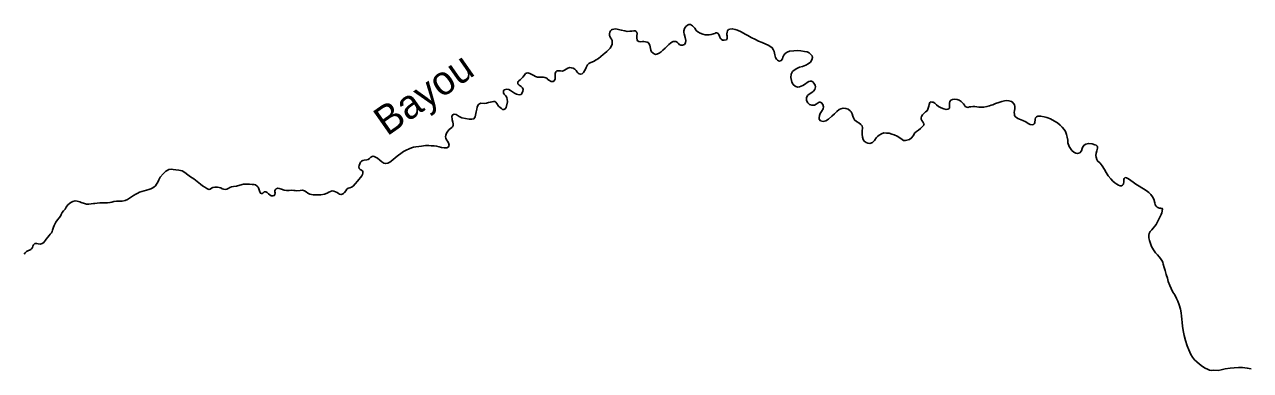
# Model space of a CAD drawing. Extents: x -939622 to -934222, y 1383701 to 1385301.
# Drawn here: x -936352.7 to -936285.2, y 1384424.2 to 1384443.3 of the extents above; entities that cross this region are included whole.
import ezdxf

# ---------------------------------------------------------------- set-up
doc = ezdxf.new("R2010")
doc.units = 0
doc.layers.add('2', color=7, linetype='Continuous')
doc.layers.add('9', color=7, linetype='Continuous')

msp = doc.modelspace()

# ---------------------------------------------------------------- linework, layer by layer
at = {"layer": '2'}
for points in [[(-936316.595, 1384442.127), (-936316.493, 1384442.124), (-936316.389, 1384442.173), (-936316.329, 1384442.265), (-936316.315, 1384442.395), (-936316.348, 1384442.56), (-936316.411, 1384442.75), (-936316.423, 1384442.822), (-936316.417, 1384442.915), (-936316.385, 1384443.046), (-936316.316, 1384443.156), (-936316.229, 1384443.238), (-936316.158, 1384443.264), (-936316.062, 1384443.27), (-936315.943, 1384443.202), (-936315.827, 1384443.074), (-936315.745, 1384442.941), (-936315.655, 1384442.863), (-936315.527, 1384442.798), (-936315.384, 1384442.746), (-936315.245, 1384442.708), (-936315.137, 1384442.703), (-936315.023, 1384442.701), (-936314.924, 1384442.713), (-936314.793, 1384442.757), (-936314.722, 1384442.783), (-936314.669, 1384442.803), (-936314.63, 1384442.81), (-936314.575, 1384442.8), (-936314.538, 1384442.771), (-936314.513, 1384442.736), (-936314.487, 1384442.677), (-936314.448, 1384442.579), (-936314.413, 1384442.505), (-936314.372, 1384442.461), (-936314.292, 1384442.403), (-936314.199, 1384442.404), (-936314.08, 1384442.423), (-936314.04, 1384442.502), (-936314.042, 1384442.65), (-936314.056, 1384442.7), (-936314.061, 1384442.754), (-936314.045, 1384442.839), (-936314.015, 1384442.924), (-936313.963, 1384442.989), (-936313.886, 1384443.019), (-936313.76, 1384443.032), (-936313.606, 1384443.001), (-936313.47, 1384442.964), (-936313.272, 1384442.874), (-936313.054, 1384442.743), (-936312.896, 1384442.658), (-936312.709, 1384442.55), (-936312.486, 1384442.435), (-936312.318, 1384442.356), (-936312.105, 1384442.276), (-936311.908, 1384442.195), (-936311.785, 1384442.13), (-936311.638, 1384442.045), (-936311.558, 1384441.985), (-936311.501, 1384441.899), (-936311.459, 1384441.78), (-936311.419, 1384441.595), (-936311.379, 1384441.452), (-936311.331, 1384441.366), (-936311.275, 1384441.299), (-936311.219, 1384441.265), (-936311.153, 1384441.246), (-936311.058, 1384441.279), (-936311.001, 1384441.372), (-936310.971, 1384441.472), (-936310.917, 1384441.576), (-936310.839, 1384441.663), (-936310.737, 1384441.745), (-936310.606, 1384441.794), (-936310.376, 1384441.811), (-936310.151, 1384441.831), (-936309.979, 1384441.812), (-936309.777, 1384441.78), (-936309.639, 1384441.764), (-936309.526, 1384441.707), (-936309.442, 1384441.635), (-936309.364, 1384441.547), (-936309.337, 1384441.455), (-936309.378, 1384441.327), (-936309.455, 1384441.195), (-936309.572, 1384441.098), (-936309.713, 1384441.021), (-936309.9, 1384440.964), (-936310.055, 1384440.919), (-936310.212, 1384440.842), (-936310.344, 1384440.756), (-936310.437, 1384440.675), (-936310.508, 1384440.531), (-936310.538, 1384440.352), (-936310.505, 1384440.188), (-936310.472, 1384440.084), (-936310.408, 1384439.966), (-936310.3, 1384439.87), (-936310.172, 1384439.817), (-936310.049, 1384439.833)], [(-936323.516, 1384440.418), (-936323.515, 1384440.49), (-936323.509, 1384440.566), (-936323.479, 1384440.654), (-936323.417, 1384440.713), (-936323.331, 1384440.722), (-936323.21, 1384440.708), (-936323.099, 1384440.703), (-936322.992, 1384440.746), (-936322.913, 1384440.815), (-936322.816, 1384440.866), (-936322.697, 1384440.894), (-936322.622, 1384440.888), (-936322.513, 1384440.861), (-936322.43, 1384440.813), (-936322.362, 1384440.74), (-936322.293, 1384440.652), (-936322.24, 1384440.597), (-936322.184, 1384440.551), (-936322.114, 1384440.532), (-936322.028, 1384440.556), (-936321.946, 1384440.616), (-936321.839, 1384440.815), (-936321.803, 1384440.909), (-936321.766, 1384440.977), (-936321.729, 1384441.047), (-936321.663, 1384441.122), (-936321.547, 1384441.183), (-936321.402, 1384441.227), (-936321.249, 1384441.319), (-936321.122, 1384441.402), (-936320.994, 1384441.503), (-936320.868, 1384441.615), (-936320.772, 1384441.694), (-936320.658, 1384441.791), (-936320.568, 1384441.878), (-936320.481, 1384441.971), (-936320.44, 1384442.027), (-936320.407, 1384442.109), (-936320.376, 1384442.167), (-936320.363, 1384442.225), (-936320.365, 1384442.3), (-936320.377, 1384442.387), (-936320.413, 1384442.461), (-936320.463, 1384442.541), (-936320.508, 1384442.62), (-936320.522, 1384442.668), (-936320.513, 1384442.758), (-936320.497, 1384442.846), (-936320.47, 1384442.913), (-936320.417, 1384442.969), (-936320.364, 1384442.998), (-936320.278, 1384443.019), (-936320.167, 1384443.023), (-936319.871, 1384442.967), (-936319.683, 1384442.922), (-936319.55, 1384442.893), (-936319.391, 1384442.899), (-936319.287, 1384442.911), (-936319.179, 1384442.924), (-936319.113, 1384442.923), (-936319.052, 1384442.892), (-936319.011, 1384442.839), (-936318.996, 1384442.756), (-936319.006, 1384442.671), (-936319.011, 1384442.572), (-936319.018, 1384442.508), (-936319.003, 1384442.424), (-936318.969, 1384442.371), (-936318.91, 1384442.337), (-936318.817, 1384442.319), (-936318.709, 1384442.335), (-936318.619, 1384442.332), (-936318.541, 1384442.323), (-936318.453, 1384442.302), (-936318.398, 1384442.27), (-936318.345, 1384442.215), (-936318.303, 1384442.123), (-936318.285, 1384442.037), (-936318.234, 1384441.852), (-936318.201, 1384441.772), (-936318.123, 1384441.684), (-936318.062, 1384441.647), (-936317.98, 1384441.623), (-936317.903, 1384441.637), (-936317.784, 1384441.686), (-936317.673, 1384441.759), (-936317.577, 1384441.853), (-936317.46, 1384441.971), (-936317.333, 1384442.102), (-936317.251, 1384442.177), (-936317.163, 1384442.243), (-936317.081, 1384442.3), (-936317.016, 1384442.329), (-936316.95, 1384442.338), (-936316.872, 1384442.331), (-936316.823, 1384442.312), (-936316.78, 1384442.283), (-936316.724, 1384442.216), (-936316.677, 1384442.163), (-936316.595, 1384442.127)], [(-936329.122, 1384437.713), (-936329.118, 1384437.788), (-936329.14, 1384437.896), (-936329.174, 1384438.009), (-936329.188, 1384438.075), (-936329.189, 1384438.096), (-936329.191, 1384438.159), (-936329.193, 1384438.216), (-936329.153, 1384438.299), (-936329.079, 1384438.334), (-936328.961, 1384438.308), (-936328.799, 1384438.193), (-936328.652, 1384438.12), (-936328.444, 1384438.082), (-936328.242, 1384438.062), (-936328.1, 1384438.045), (-936327.984, 1384438.079), (-936327.91, 1384438.19), (-936327.868, 1384438.463), (-936327.821, 1384438.605), (-936327.801, 1384438.708), (-936327.771, 1384438.8), (-936327.731, 1384438.864), (-936327.675, 1384438.899), (-936327.595, 1384438.935), (-936327.394, 1384438.924), (-936327.298, 1384438.936), (-936327.182, 1384438.964), (-936327.078, 1384438.992), (-936326.985, 1384439.013), (-936326.913, 1384439.024), (-936326.838, 1384439.018), (-936326.78, 1384438.984), (-936326.721, 1384438.914), (-936326.626, 1384438.778), (-936326.536, 1384438.697), (-936326.471, 1384438.633), (-936326.401, 1384438.593), (-936326.329, 1384438.593), (-936326.258, 1384438.619), (-936326.2, 1384438.697), (-936326.144, 1384439.008), (-936326.152, 1384439.149), (-936326.17, 1384439.227), (-936326.186, 1384439.278), (-936326.243, 1384439.357), (-936326.312, 1384439.436), (-936326.346, 1384439.489), (-936326.361, 1384439.561), (-936326.356, 1384439.615), (-936326.31, 1384439.668), (-936326.239, 1384439.697), (-936326.164, 1384439.706), (-936326.062, 1384439.688), (-936325.964, 1384439.634), (-936325.752, 1384439.479), (-936325.645, 1384439.431), (-936325.563, 1384439.41), (-936325.452, 1384439.396), (-936325.383, 1384439.416), (-936325.326, 1384439.508), (-936325.287, 1384439.603), (-936325.281, 1384439.687), (-936325.308, 1384439.774), (-936325.379, 1384439.847), (-936325.441, 1384439.893), (-936325.493, 1384439.924), (-936325.53, 1384439.959), (-936325.562, 1384440.009), (-936325.569, 1384440.051), (-936325.567, 1384440.087), (-936325.551, 1384440.13), (-936325.507, 1384440.161), (-936325.434, 1384440.215), (-936325.361, 1384440.29), (-936325.289, 1384440.37), (-936325.22, 1384440.466), (-936325.183, 1384440.524), (-936325.136, 1384440.568), (-936325.089, 1384440.594), (-936325.014, 1384440.602), (-936324.911, 1384440.579), (-936324.792, 1384440.516), (-936324.682, 1384440.457), (-936324.587, 1384440.406), (-936324.475, 1384440.374), (-936324.373, 1384440.365), (-936324.283, 1384440.371), (-936324.169, 1384440.375), (-936324.078, 1384440.354), (-936323.977, 1384440.306), (-936323.909, 1384440.248), (-936323.829, 1384440.185), (-936323.771, 1384440.145), (-936323.722, 1384440.128), (-936323.677, 1384440.124), (-936323.626, 1384440.126), (-936323.582, 1384440.151), (-936323.542, 1384440.201), (-936323.519, 1384440.25), (-936323.516, 1384440.418)], [(-936310.049, 1384439.833), (-936309.866, 1384439.915), (-936309.73, 1384439.997), (-936309.634, 1384440.067), (-936309.537, 1384440.13), (-936309.459, 1384440.154), (-936309.393, 1384440.15), (-936309.317, 1384440.105), (-936309.258, 1384440.041), (-936309.191, 1384439.932), (-936309.179, 1384439.83), (-936309.219, 1384439.687), (-936309.288, 1384439.597), (-936309.379, 1384439.528), (-936309.519, 1384439.424), (-936309.607, 1384439.355), (-936309.675, 1384439.22), (-936309.679, 1384439.076), (-936309.606, 1384438.949), (-936309.501, 1384438.865), (-936309.371, 1384438.824), (-936309.239, 1384438.832), (-936309.132, 1384438.886), (-936309.035, 1384438.95), (-936308.967, 1384438.982), (-936308.914, 1384438.993), (-936308.841, 1384438.959), (-936308.774, 1384438.853), (-936308.734, 1384438.734), (-936308.76, 1384438.622), (-936308.843, 1384438.472), (-936308.911, 1384438.364), (-936308.959, 1384438.26), (-936308.979, 1384438.133), (-936308.976, 1384438.061), (-936308.892, 1384437.962), (-936308.759, 1384437.93), (-936308.607, 1384437.959), (-936308.454, 1384438.058), (-936308.27, 1384438.218), (-936308.136, 1384438.348), (-936308.005, 1384438.473), (-936307.88, 1384438.583), (-936307.782, 1384438.631), (-936307.645, 1384438.654), (-936307.503, 1384438.65), (-936307.376, 1384438.603), (-936307.274, 1384438.519), (-936307.209, 1384438.452), (-936307.157, 1384438.355), (-936307.12, 1384438.226), (-936307.09, 1384438.131), (-936307.026, 1384438.01), (-936306.912, 1384437.924), (-936306.796, 1384437.849), (-936306.676, 1384437.76), (-936306.613, 1384437.678), (-936306.585, 1384437.577), (-936306.597, 1384437.39), (-936306.598, 1384437.218), (-936306.587, 1384437.068), (-936306.555, 1384436.94), (-936306.498, 1384436.845), (-936306.385, 1384436.765), (-936306.287, 1384436.726), (-936306.182, 1384436.718), (-936306.042, 1384436.768), (-936305.935, 1384436.873), (-936305.826, 1384437.022), (-936305.759, 1384437.105), (-936305.675, 1384437.18), (-936305.533, 1384437.248), (-936305.405, 1384437.292), (-936305.264, 1384437.29), (-936305.119, 1384437.274), (-936304.98, 1384437.231), (-936304.846, 1384437.184), (-936304.685, 1384437.123), (-936304.529, 1384437.032), (-936304.403, 1384436.937), (-936304.323, 1384436.886), (-936304.226, 1384436.871), (-936303.994, 1384436.927), (-936303.883, 1384437.021), (-936303.797, 1384437.132), (-936303.697, 1384437.292), (-936303.621, 1384437.37), (-936303.51, 1384437.449), (-936303.399, 1384437.531), (-936303.317, 1384437.612), (-936303.247, 1384437.678), (-936303.216, 1384437.73), (-936303.202, 1384437.76), (-936303.2, 1384437.788), (-936303.223, 1384437.841), (-936303.261, 1384437.906), (-936303.326, 1384437.985), (-936303.362, 1384438.059), (-936303.361, 1384438.128), (-936303.336, 1384438.195), (-936303.285, 1384438.287)], [(-936303.285, 1384438.287), (-936303.21, 1384438.365), (-936303.111, 1384438.449), (-936303.035, 1384438.518), (-936302.993, 1384438.607), (-936302.929, 1384438.763), (-936302.911, 1384438.862), (-936302.906, 1384438.908), (-936302.887, 1384438.963), (-936302.838, 1384439.003), (-936302.774, 1384438.999), (-936302.693, 1384438.987), (-936302.61, 1384438.933), (-936302.511, 1384438.849), (-936302.403, 1384438.756), (-936302.25, 1384438.674), (-936302.101, 1384438.622), (-936301.989, 1384438.59), (-936301.897, 1384438.599), (-936301.828, 1384438.619), (-936301.8, 1384438.662), (-936301.79, 1384438.744), (-936301.802, 1384438.837), (-936301.802, 1384438.933), (-936301.781, 1384439.024), (-936301.718, 1384439.095), (-936301.623, 1384439.144), (-936301.537, 1384439.162), (-936301.377, 1384439.143), (-936301.267, 1384439.096), (-936301.163, 1384439.03), (-936301.074, 1384438.961), (-936301.024, 1384438.893), (-936300.976, 1384438.82), (-936300.929, 1384438.758), (-936300.846, 1384438.71), (-936300.789, 1384438.703), (-936300.688, 1384438.724), (-936300.613, 1384438.742), (-936300.518, 1384438.757), (-936300.406, 1384438.749), (-936300.183, 1384438.72), (-936300.045, 1384438.713), (-936299.907, 1384438.72), (-936299.74, 1384438.747), (-936299.597, 1384438.794), (-936299.505, 1384438.818), (-936299.416, 1384438.848), (-936299.262, 1384438.914), (-936299.087, 1384438.974), (-936298.923, 1384439.031), (-936298.774, 1384439.063), (-936298.64, 1384439.073), (-936298.525, 1384439.065), (-936298.392, 1384439.031), (-936298.309, 1384438.964), (-936298.218, 1384438.835), (-936298.203, 1384438.751), (-936298.195, 1384438.622), (-936298.214, 1384438.534), (-936298.228, 1384438.428), (-936298.225, 1384438.338), (-936298.211, 1384438.26), (-936298.16, 1384438.184), (-936298.025, 1384438.098), (-936297.766, 1384437.978), (-936297.598, 1384437.899), (-936297.473, 1384437.819), (-936297.356, 1384437.757), (-936297.239, 1384437.746), (-936297.179, 1384437.76), (-936297.129, 1384437.795), (-936297.098, 1384437.853), (-936297.078, 1384438.055), (-936297.053, 1384438.125), (-936297.01, 1384438.187), (-936296.933, 1384438.219), (-936296.777, 1384438.219), (-936296.581, 1384438.174), (-936296.436, 1384438.149), (-936296.241, 1384438.068), (-936296.008, 1384437.938), (-936295.855, 1384437.85), (-936295.701, 1384437.717), (-936295.586, 1384437.615), (-936295.477, 1384437.492), (-936295.413, 1384437.371), (-936295.36, 1384437.217), (-936295.31, 1384437.059), (-936295.287, 1384436.903), (-936295.273, 1384436.75), (-936295.215, 1384436.554), (-936295.13, 1384436.43), (-936295.058, 1384436.336), (-936294.953, 1384436.243), (-936294.842, 1384436.178), (-936294.755, 1384436.163), (-936294.624, 1384436.197), (-936294.534, 1384436.3), (-936294.491, 1384436.434), (-936294.458, 1384436.537)], [(-936337.727, 1384434.112), (-936337.557, 1384434.124), (-936337.431, 1384434.137), (-936337.317, 1384434.111), (-936337.222, 1384434.054), (-936337.129, 1384433.979), (-936337.01, 1384433.919), (-936336.838, 1384433.886), (-936336.648, 1384433.878), (-936336.415, 1384433.891), (-936336.209, 1384433.926), (-936336.063, 1384433.979), (-936335.978, 1384434.024), (-936335.88, 1384434.069), (-936335.791, 1384434.096), (-936335.703, 1384434.084), (-936335.612, 1384434.057), (-936335.521, 1384434.006), (-936335.447, 1384433.957), (-936335.377, 1384433.918), (-936335.298, 1384433.902), (-936335.23, 1384433.926), (-936335.171, 1384433.961), (-936335.113, 1384434.02), (-936335.044, 1384434.109), (-936334.984, 1384434.196), (-936334.907, 1384434.243), (-936334.824, 1384434.273), (-936334.732, 1384434.31), (-936334.641, 1384434.37), (-936334.522, 1384434.482), (-936334.397, 1384434.631), (-936334.317, 1384434.733), (-936334.233, 1384434.838), (-936334.161, 1384434.934), (-936334.124, 1384435.001), (-936334.094, 1384435.071), (-936334.093, 1384435.15), (-936334.122, 1384435.206), (-936334.18, 1384435.24), (-936334.247, 1384435.271), (-936334.304, 1384435.335), (-936334.325, 1384435.428), (-936334.309, 1384435.509), (-936334.273, 1384435.601), (-936334.234, 1384435.677), (-936334.179, 1384435.733), (-936334.108, 1384435.769), (-936334.025, 1384435.796), (-936333.884, 1384435.813), (-936333.813, 1384435.83), (-936333.739, 1384435.881), (-936333.655, 1384435.959), (-936333.593, 1384436), (-936333.536, 1384436.011), (-936333.485, 1384435.998), (-936333.286, 1384435.902), (-936333.166, 1384435.798), (-936333.055, 1384435.696), (-936332.947, 1384435.631), (-936332.845, 1384435.61), (-936332.728, 1384435.635), (-936332.613, 1384435.684), (-936332.449, 1384435.804), (-936332.303, 1384435.938), (-936332.142, 1384436.061), (-936332.004, 1384436.162), (-936331.857, 1384436.263), (-936331.707, 1384436.35), (-936331.556, 1384436.418), (-936331.423, 1384436.477), (-936331.304, 1384436.514), (-936331.176, 1384436.536), (-936331.02, 1384436.553), (-936330.877, 1384436.567), (-936330.646, 1384436.596), (-936330.475, 1384436.602), (-936330.337, 1384436.592), (-936330.171, 1384436.576), (-936330.039, 1384436.566), (-936329.897, 1384436.537), (-936329.76, 1384436.5), (-936329.612, 1384436.472), (-936329.537, 1384436.468), (-936329.471, 1384436.474), (-936329.409, 1384436.503), (-936329.366, 1384436.558), (-936329.35, 1384436.616), (-936329.384, 1384436.741), (-936329.441, 1384436.833), (-936329.495, 1384436.918), (-936329.537, 1384436.998), (-936329.554, 1384437.078), (-936329.531, 1384437.179), (-936329.489, 1384437.282), (-936329.421, 1384437.399), (-936329.343, 1384437.486), (-936329.272, 1384437.542), (-936329.208, 1384437.59), (-936329.156, 1384437.64), (-936329.122, 1384437.713)], [(-936294.458, 1384436.537), (-936294.383, 1384436.627), (-936294.285, 1384436.675), (-936294.146, 1384436.713), (-936293.941, 1384436.687), (-936293.792, 1384436.644), (-936293.722, 1384436.613), (-936293.672, 1384436.57), (-936293.656, 1384436.534), (-936293.651, 1384436.456), (-936293.679, 1384436.311), (-936293.714, 1384436.183), (-936293.731, 1384436.056), (-936293.728, 1384435.966), (-936293.693, 1384435.832), (-936293.652, 1384435.755), (-936293.503, 1384435.622), (-936293.39, 1384435.475), (-936293.255, 1384435.281), (-936293.174, 1384435.106), (-936293.066, 1384434.935), (-936292.92, 1384434.769), (-936292.801, 1384434.64), (-936292.687, 1384434.536), (-936292.588, 1384434.464), (-936292.5, 1384434.419), (-936292.4, 1384434.386), (-936292.324, 1384434.383), (-936292.268, 1384434.412), (-936292.222, 1384434.477), (-936292.197, 1384434.61), (-936292.192, 1384434.727), (-936292.179, 1384434.785), (-936292.132, 1384434.832), (-936292.051, 1384434.828), (-936291.932, 1384434.769), (-936291.688, 1384434.579), (-936291.532, 1384434.473), (-936291.354, 1384434.358), (-936290.974, 1384434.131), (-936290.817, 1384434.019), (-936290.706, 1384433.911), (-936290.623, 1384433.781), (-936290.547, 1384433.637), (-936290.492, 1384433.437), (-936290.465, 1384433.336), (-936290.408, 1384433.259), (-936290.358, 1384433.21), (-936290.288, 1384433.173), (-936290.228, 1384433.157), (-936290.173, 1384433.147), (-936290.137, 1384433.139), (-936290.083, 1384433.135), (-936290.067, 1384433.102), (-936290.108, 1384432.899), (-936290.15, 1384432.796), (-936290.208, 1384432.655), (-936290.281, 1384432.511), (-936290.349, 1384432.389), (-936290.426, 1384432.248), (-936290.495, 1384432.164), (-936290.584, 1384432.044), (-936290.653, 1384431.96), (-936290.74, 1384431.858), (-936290.8, 1384431.754), (-936290.818, 1384431.66), (-936290.819, 1384431.515), (-936290.79, 1384431.375), (-936290.734, 1384431.205), (-936290.668, 1384431.039), (-936290.566, 1384430.844), (-936290.452, 1384430.688), (-936290.347, 1384430.577), (-936290.244, 1384430.461), (-936290.172, 1384430.373), (-936290.096, 1384430.261), (-936290.051, 1384430.166), (-936290.029, 1384430.062), (-936289.97, 1384429.886), (-936289.913, 1384429.723), (-936289.858, 1384429.493), (-936289.8, 1384429.287), (-936289.752, 1384429.114), (-936289.67, 1384428.894), (-936289.595, 1384428.716), (-936289.495, 1384428.524), (-936289.394, 1384428.365), (-936289.289, 1384428.176), (-936289.233, 1384428.031), (-936289.157, 1384427.826), (-936289.071, 1384427.588), (-936289.047, 1384427.384), (-936289.016, 1384427.198), (-936289.008, 1384427.036), (-936288.993, 1384426.841), (-936288.962, 1384426.638), (-936288.924, 1384426.41), (-936288.867, 1384426.126), (-936288.798, 1384425.861), (-936288.704, 1384425.566), (-936288.619, 1384425.334)], [(-936346.148, 1384434.111), (-936346.014, 1384434.145), (-936345.886, 1384434.179), (-936345.778, 1384434.21), (-936345.695, 1384434.245), (-936345.613, 1384434.299), (-936345.519, 1384434.38), (-936345.453, 1384434.472), (-936345.393, 1384434.588), (-936345.34, 1384434.707), (-936345.254, 1384434.854), (-936345.098, 1384435.039), (-936345.028, 1384435.107), (-936344.949, 1384435.179), (-936344.869, 1384435.232), (-936344.783, 1384435.271), (-936344.658, 1384435.29), (-936344.537, 1384435.275), (-936344.405, 1384435.261), (-936344.237, 1384435.245), (-936344.055, 1384435.208), (-936343.897, 1384435.12), (-936343.74, 1384434.995), (-936343.584, 1384434.879), (-936343.412, 1384434.767), (-936343.228, 1384434.619), (-936343.044, 1384434.477), (-936342.924, 1384434.388), (-936342.804, 1384434.301), (-936342.697, 1384434.229), (-936342.618, 1384434.189), (-936342.57, 1384434.182), (-936342.51, 1384434.205), (-936342.434, 1384434.249), (-936342.354, 1384434.29), (-936342.232, 1384434.315), (-936342.111, 1384434.301), (-936342.006, 1384434.286), (-936341.921, 1384434.261), (-936341.842, 1384434.218), (-936341.76, 1384434.188), (-936341.666, 1384434.173), (-936341.595, 1384434.187), (-936341.482, 1384434.253), (-936341.427, 1384434.291), (-936341.341, 1384434.333), (-936341.215, 1384434.348), (-936341.051, 1384434.368), (-936340.872, 1384434.422), (-936340.673, 1384434.467), (-936340.523, 1384434.471), (-936340.336, 1384434.465), (-936340.201, 1384434.46), (-936340.087, 1384434.445), (-936340.014, 1384434.426), (-936339.928, 1384434.366), (-936339.866, 1384434.298), (-936339.834, 1384434.212), (-936339.778, 1384434.051), (-936339.743, 1384433.977), (-936339.682, 1384433.955), (-936339.637, 1384433.962), (-936339.602, 1384433.984), (-936339.576, 1384434.015), (-936339.529, 1384434.041), (-936339.448, 1384434.046), (-936339.366, 1384434.018), (-936339.295, 1384433.948), (-936339.224, 1384433.887), (-936339.144, 1384433.836), (-936339.051, 1384433.82), (-936338.977, 1384433.841), (-936338.943, 1384433.908), (-936338.933, 1384433.992), (-936338.941, 1384434.049), (-936338.943, 1384434.112), (-936338.929, 1384434.167), (-936338.877, 1384434.223), (-936338.784, 1384434.246), (-936338.703, 1384434.237), (-936338.582, 1384434.195), (-936338.43, 1384434.134), (-936338.312, 1384434.116), (-936338.162, 1384434.117), (-936338.049, 1384434.136), (-936337.908, 1384434.128), (-936337.832, 1384434.121), (-936337.727, 1384434.112)], [(-936352.758, 1384430.615), (-936352.688, 1384430.695), (-936352.612, 1384430.755), (-936352.511, 1384430.812), (-936352.446, 1384430.838), (-936352.39, 1384430.867), (-936352.34, 1384430.91), (-936352.297, 1384430.981), (-936352.263, 1384431.051), (-936352.23, 1384431.136), (-936352.163, 1384431.195), (-936352.115, 1384431.209), (-936352.055, 1384431.208), (-936351.97, 1384431.186), (-936351.868, 1384431.174), (-936351.754, 1384431.195), (-936351.675, 1384431.261), (-936351.539, 1384431.433), (-936351.447, 1384431.553), (-936351.374, 1384431.637), (-936351.31, 1384431.708), (-936351.25, 1384431.791), (-936351.21, 1384431.861), (-936351.191, 1384431.931), (-936351.136, 1384432.095), (-936351.1, 1384432.195), (-936351, 1384432.382), (-936350.914, 1384432.505), (-936350.818, 1384432.61), (-936350.755, 1384432.708), (-936350.709, 1384432.803), (-936350.658, 1384432.903), (-936350.574, 1384432.993), (-936350.499, 1384433.101), (-936350.433, 1384433.211), (-936350.344, 1384433.325), (-936350.256, 1384433.406), (-936350.171, 1384433.468), (-936350.07, 1384433.519), (-936349.948, 1384433.553), (-936349.834, 1384433.541), (-936349.686, 1384433.501), (-936349.607, 1384433.467), (-936349.434, 1384433.397), (-936349.316, 1384433.373), (-936349.186, 1384433.362), (-936349.061, 1384433.381), (-936348.924, 1384433.403), (-936348.855, 1384433.414), (-936348.726, 1384433.433), (-936348.583, 1384433.446), (-936348.454, 1384433.447), (-936348.343, 1384433.447), (-936348.16, 1384433.45), (-936348.025, 1384433.46), (-936347.915, 1384433.484), (-936347.808, 1384433.515), (-936347.673, 1384433.534), (-936347.508, 1384433.526), (-936347.349, 1384433.537), (-936347.194, 1384433.572), (-936347.057, 1384433.621), (-936346.94, 1384433.697), (-936346.84, 1384433.769), (-936346.722, 1384433.845), (-936346.604, 1384433.917), (-936346.489, 1384433.981), (-936346.394, 1384434.026), (-936346.272, 1384434.069), (-936346.148, 1384434.111)], [(-936288.619, 1384425.334), (-936288.506, 1384425.091), (-936288.419, 1384424.935), (-936288.298, 1384424.798), (-936288.171, 1384424.688), (-936288.029, 1384424.56), (-936287.865, 1384424.418), (-936287.721, 1384424.339), (-936287.584, 1384424.268), (-936287.483, 1384424.226), (-936287.363, 1384424.212), (-936287.249, 1384424.216), (-936287.011, 1384424.203), (-936286.838, 1384424.242), (-936286.612, 1384424.298), (-936286.337, 1384424.325), (-936286.13, 1384424.345), (-936285.891, 1384424.374), (-936285.669, 1384424.372), (-936285.398, 1384424.339), (-936285.189, 1384424.301)]]:
    msp.add_lwpolyline(points, dxfattribs=at)

# ---------------------------------------------------------------- texts
at = {"layer": '9'}
msp.add_text('Bayou', height=1.584, rotation=35, dxfattribs=at).set_placement((-936332.765, 1384437.091))

doc.saveas('drawing.dxf')
